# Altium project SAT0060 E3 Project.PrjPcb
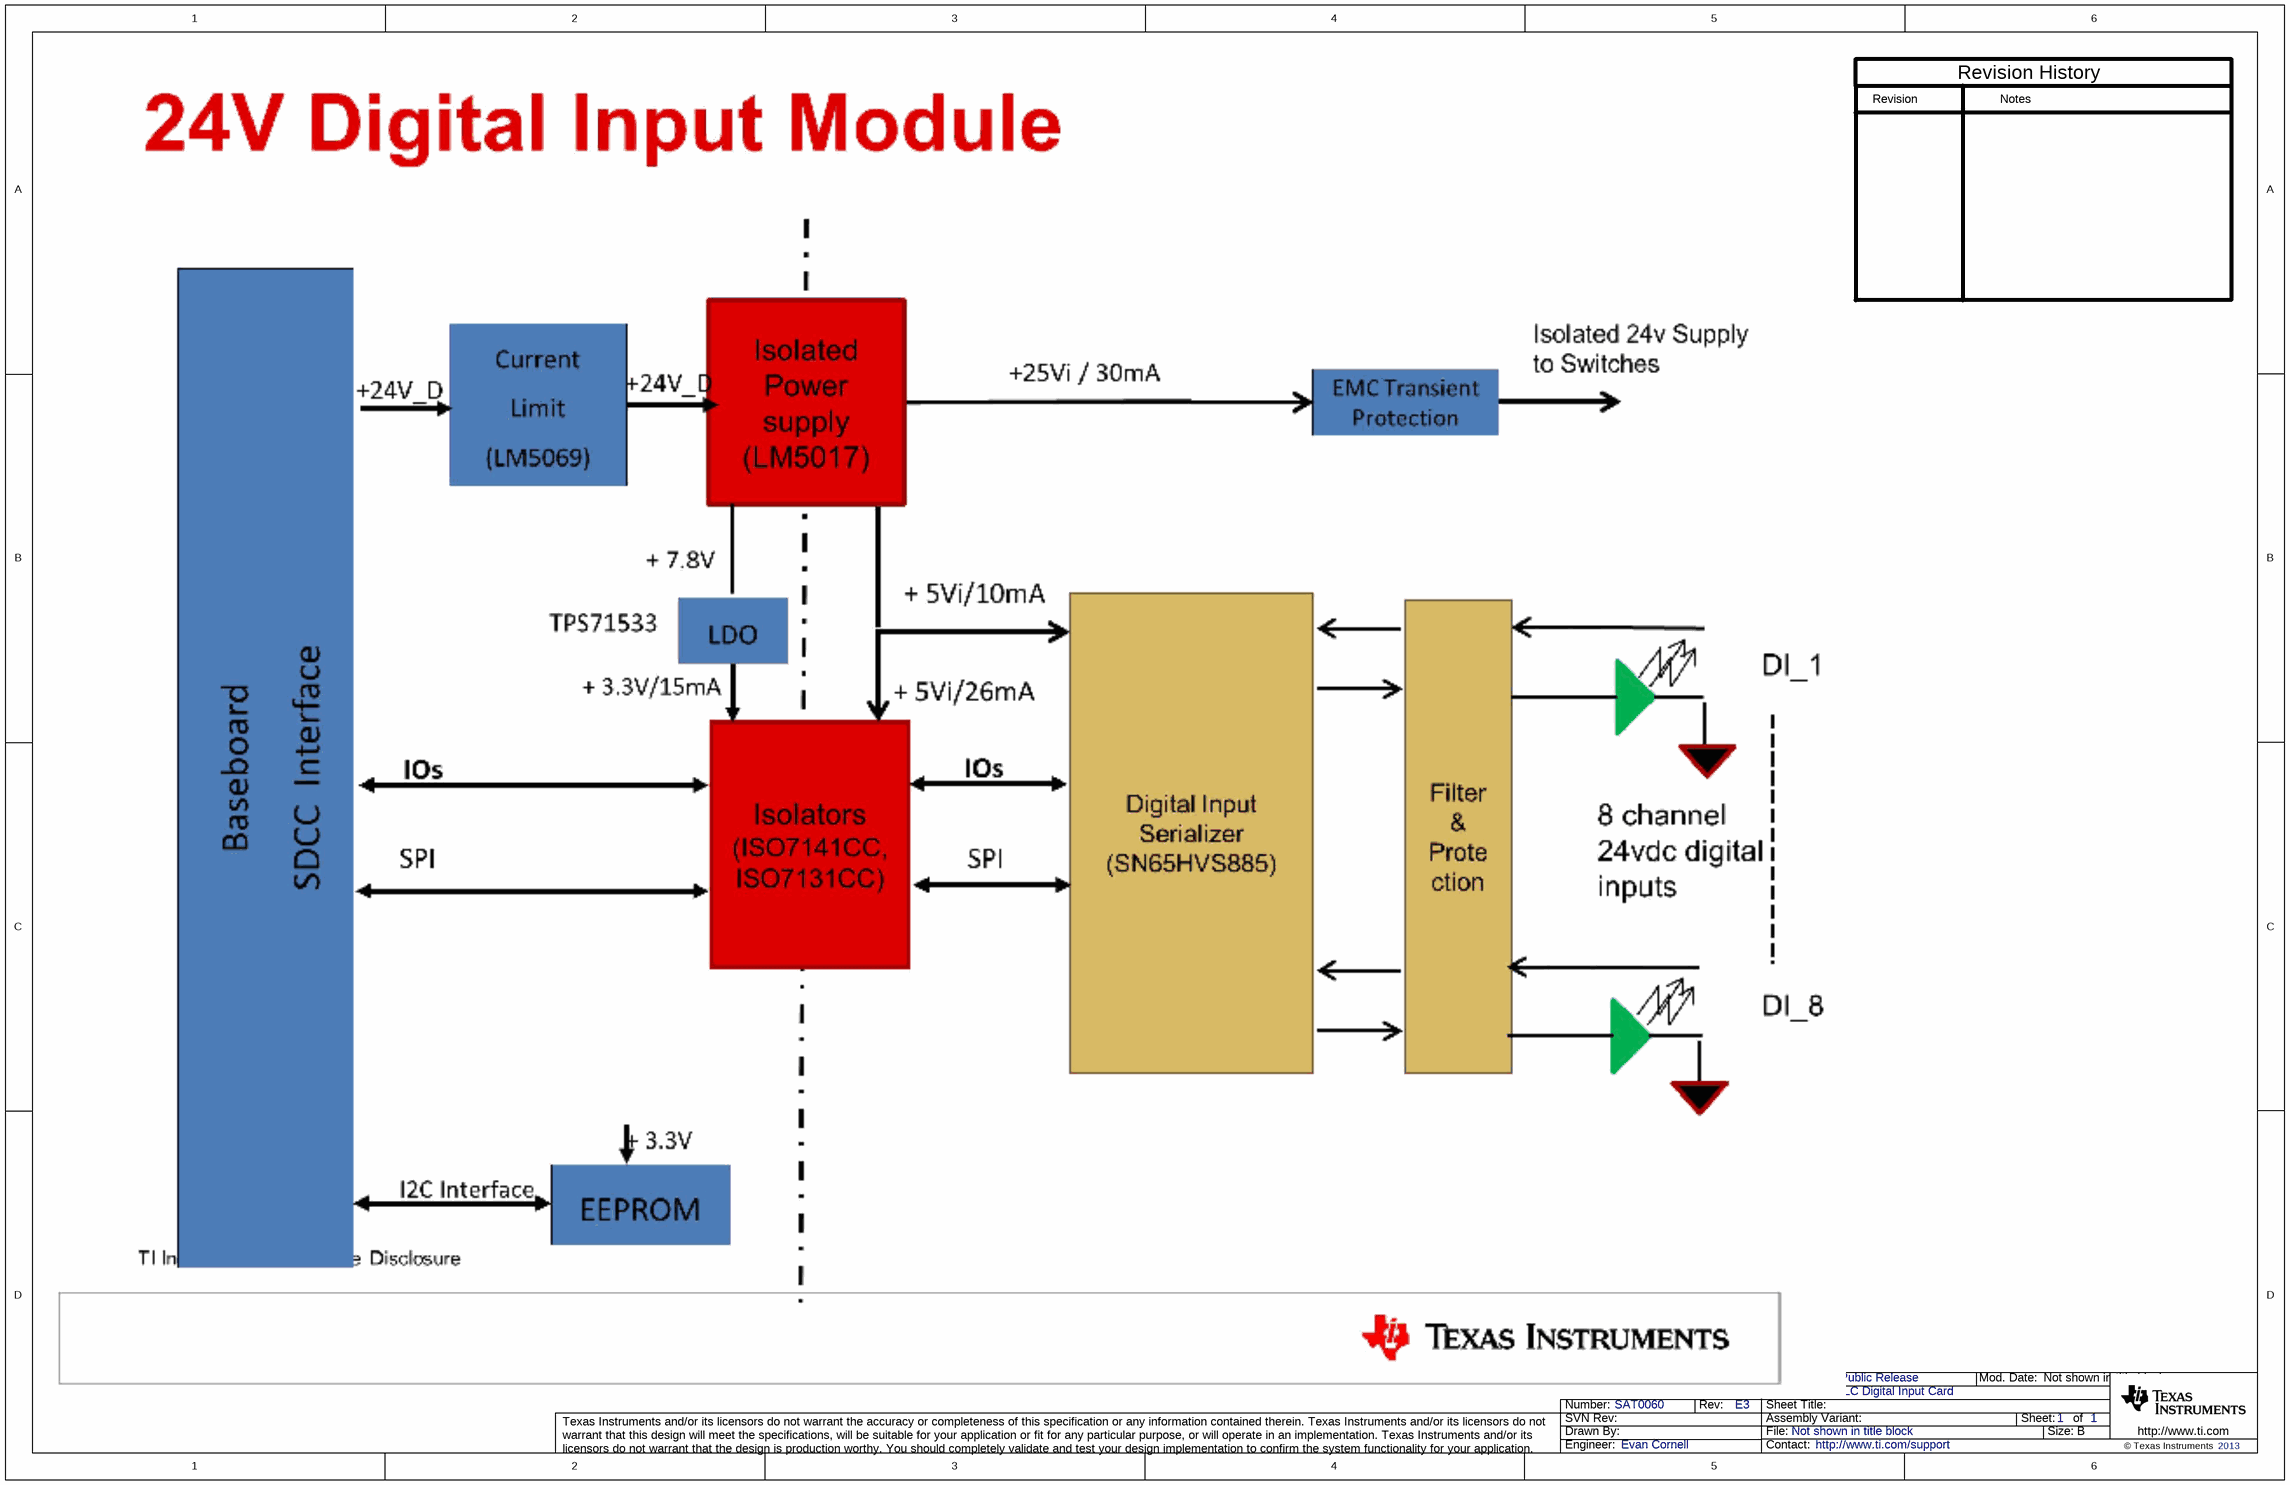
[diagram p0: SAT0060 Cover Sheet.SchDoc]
TechSupport: http://www.ti.com/support; SCH_Rev: E3; PRJ_Title: PLC Digital Input Card; PRJ_Number: SAT0060; PRJ_Engineer: Evan Cornell; PRJ_Customer: Public Release; PCB_Rev: E3; PCB_Layout: TI India; CopyrightYear: 2013
4 sheets, 137 parts. Net scope: global (net labels, ports and power ports of the same name join across sheets).
Board file: SAT0060 E3 PCB.PcbDoc
Sheets:
  SAT0060 Cover Sheet.SchDoc
  SAT0060 Sheet1.SchDoc
  SAT0060 Sheet2.SchDoc
  Hardware_ANSI-B.SchDoc

## Sheet SAT0060 Cover Sheet.SchDoc
size 431 x 279 mm; Date: Not shown in title block; ApprovedBy: Not shown in title block; CheckedBy: Not shown in title block; Author: Not shown in title block; CompanyName: Not shown in title block; Engineer: Not shown in title block; Organization: Not shown in title block; Address1: Not shown in title block; Address2: Not shown in title block; Address3: Not shown in title block; Address4: Not shown in title block; DocumentNumber: 1; Revision: Use project parameter SCH_Rev; SheetNumber: 1; SheetTotal: 1; PageSetup: Record=PageOptions|CenterHorizontal=True|CenterVertical=True|PrintScale=0.96|XCorrection=1.00|YCorrection=1.00|PrintKind=0|BorderSize=5000000|LeftOffset=0|BottomOffset=0|Orientation=2|PaperLength=1000|PaperWidth=1000|Scale=100|PaperSource=15|PrintQuality=600|MediaType=1|DitherType=10|PaperKind=11x17|PrintScaleMode=1

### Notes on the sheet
- Revision
- Notes
- Revision History

## Sheet SAT0060 Sheet1.SchDoc
size 431 x 279 mm; Date: Not shown in title block; ApprovedBy: Not shown in title block; CheckedBy: Not shown in title block; Author: Not shown in title block; CompanyName: Not shown in title block; Engineer: Not shown in title block; Organization: Not shown in title block; Address1: Not shown in title block; Address2: Not shown in title block; Address3: Not shown in title block; Address4: Not shown in title block; DocumentNumber: 1; Revision: Use project parameter SCH_Rev; SheetNumber: 1; SheetTotal: 1; PageSetup: Record=PageOptions|CenterHorizontal=True|CenterVertical=True|PrintScale=0.96|XCorrection=1.00|YCorrection=1.00|PrintKind=0|BorderSize=5000000|LeftOffset=0|BottomOffset=0|Orientation=2|PaperLength=1000|PaperWidth=1000|Scale=100|PaperSource=15|PrintQuality=600|MediaType=1|DitherType=10|PaperKind=11x17|PrintScaleMode=1
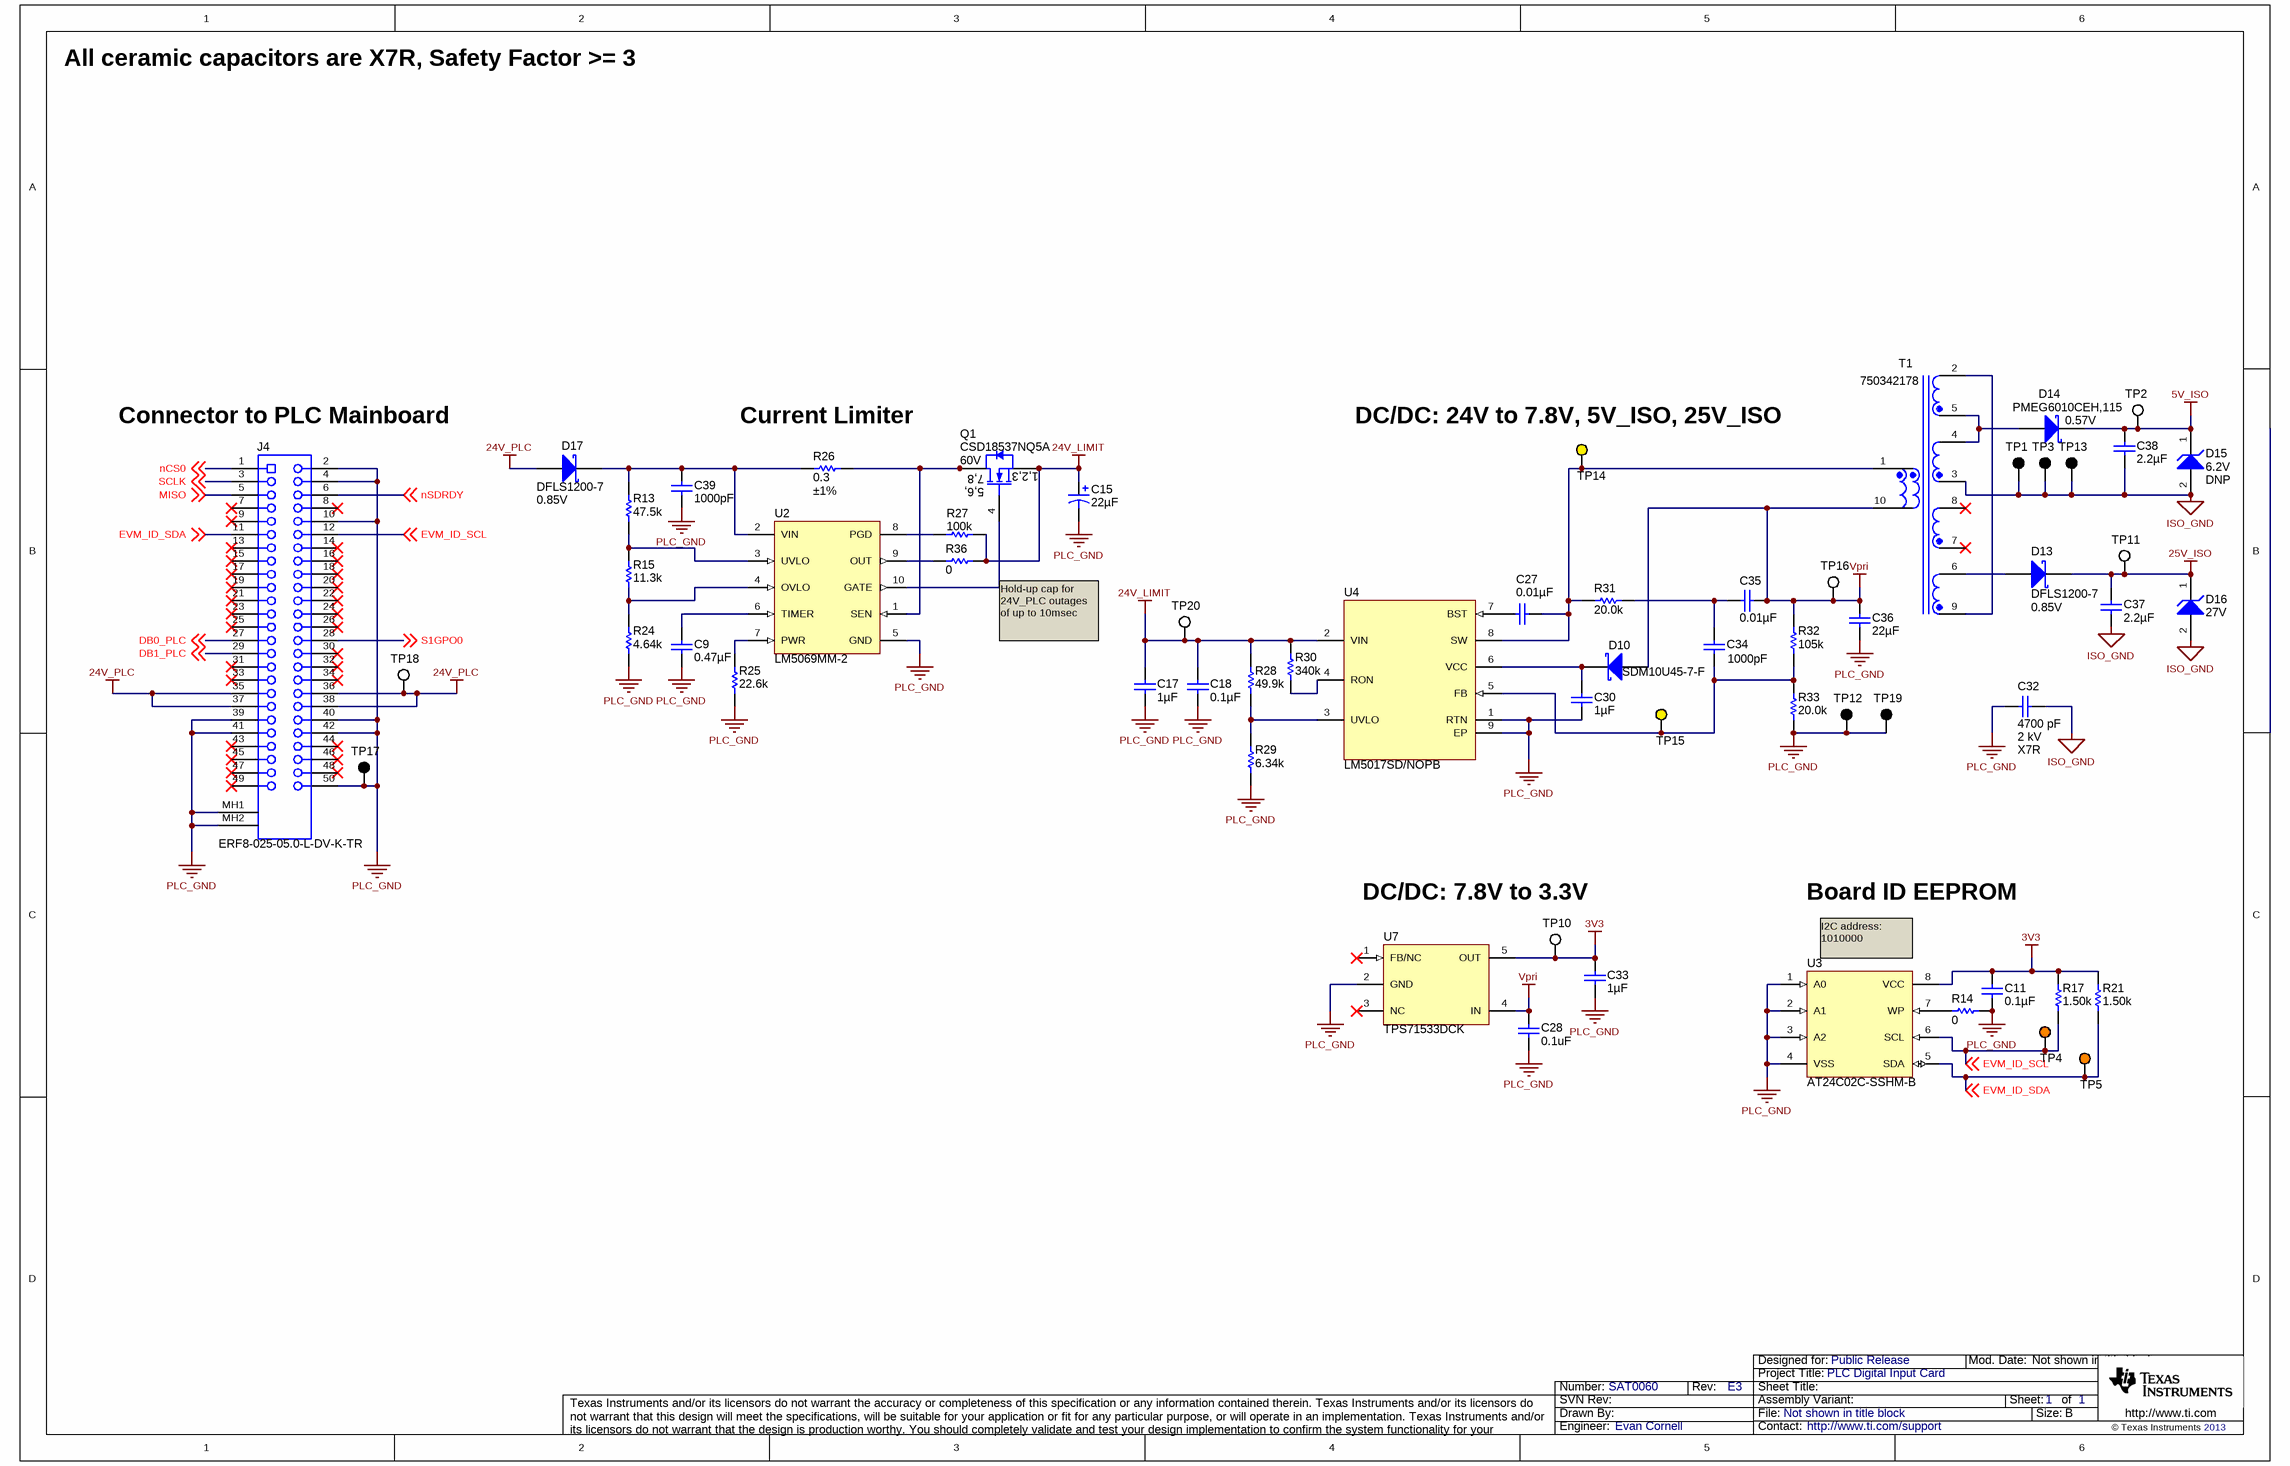
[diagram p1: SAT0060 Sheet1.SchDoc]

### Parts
C9  ValueDisplayed: 0.47µF  [0805_HV]  (hidden comment: 0805YC474JAT2A)
C11  ValueDisplayed: 0.1µF  [0402]  (hidden comment: GRM155R71C104KA88D)
C15  ValueDisplayed: 22µF  [SM_RADIAL_D]  (hidden comment: EEE-FK1H220P)
C17  ValueDisplayed: 1µF  [1206]  (hidden comment: GRM31CR72A105KA01L)
C18  ValueDisplayed: 0.1µF  [0603]  (hidden comment: GRM188R72A104KA35D)
C27  ValueDisplayed: 0.01µF  [0402]  (hidden comment: C1005X7R1C103K)
C28  value 0.1uF  [0603]  (hidden comment: GRM188R71E104KA01D)
C30  ValueDisplayed: 1µF  [0603]  (hidden comment: C1608X7R1C105K)
C32  value 4700 pF  VDC_V: 2 kV  TempCo: X7R  [1210]  (hidden comment: Used in BOM report)
C33  ValueDisplayed: 1µF  [0603]  (hidden comment: GRM188R71C105KA12D)
C34  ValueDisplayed: 1000pF  [0603]  (hidden comment: GRM188R71E102KA01D)
C35  ValueDisplayed: 0.01µF  [0402]  (hidden comment: GRM155R71H103KA88D)
C36  ValueDisplayed: 22µF  [1210]  (hidden comment: GRM32ER71E226KE15L)
C37  ValueDisplayed: 2.2µF  [0805_HV]  (hidden comment: GRM21BR71E225KA73L)
C38  ValueDisplayed: 2.2µF  [0805_HV]  (hidden comment: GRM21BR71E225KA73L)
C39  ValueDisplayed: 1000pF  [0402]  (hidden comment: GRM155R72A102KA01D)
D10  SDM10U45-7-F  [SOD-523]
D13  DFLS1200-7  Value2: 0.85V  [powerDI123]
D14  PMEG6010CEH,115  Value2: 0.57V  [SOD-123F]
D15  value 6.2V  [SOD-123]  (hidden comment: MMSZ5234B-7-F)
D16  value 27V  [SOD-123]  (hidden comment: MMSZ5254B-7-F)
D17  DFLS1200-7  Value2: 0.85V  [powerDI123]
J4  ERF8-025-05.0-L-DV-K-TR  [CONN_ERF8-025-05_0-L-DV-L-TR]
Q1  CSD18537NQ5A  value 60V  [TRANS_NexFET_Q5A]
R13  value 47.5k  [0402]  (hidden comment: CRCW040247K5FKED)
R14  value 0  [0402]  (hidden comment: CRCW04020000Z0ED)
R15  value 11.3k  [0402]  (hidden comment: CRCW040211K3FKED)
R17  value 1.50k  [0402]  (hidden comment: CRCW04021K50FKED)
R21  value 1.50k  [0402]  (hidden comment: CRCW04021K50FKED)
R24  value 4.64k  [0402]  (hidden comment: CRCW04024K64FKED)
R25  value 22.6k  [0402]  (hidden comment: CRCW040222K6FKED)
R26  value 0.3  Tolerance_%: ±1%  [0402]  (hidden comment: Used in BOM report)
R27  value 100k  [0402]  (hidden comment: CRCW0402100KFKED)
R28  value 49.9k  [0402]  (hidden comment: CRCW040249K9FKED)
R29  value 6.34k  [0402]  (hidden comment: CRCW04026K34FKED)
R30  value 340k  [0402]  (hidden comment: CRCW0402340KFKED)
R31  value 20.0k  [0402]  (hidden comment: CRCW040220K0FKED)
R32  value 105k  [0402]  (hidden comment: CRCW0402105KFKED)
R33  value 20.0k  [0402]  (hidden comment: CRCW040220K0FKED)
R36  value 0  [0402]  (hidden comment: CRCW04020000Z0ED)
T1  750342178  [Wurth_750342178]
TP1  5001  [Keystone5001]  (value not drawn)
TP2  5002  [Keystone5002]  (value not drawn)
TP3  5001  [Keystone5001]  (value not drawn)
TP4  5003  [Keystone5003]  (value not drawn)
TP5  5003  [Keystone5003]  (value not drawn)
TP10  5002  [Keystone5002]  (value not drawn)
TP11  5002  [Keystone5002]  (value not drawn)
TP12  5001  [Keystone5001]  (value not drawn)
TP13  5001  [Keystone5001]  (value not drawn)
TP14  5004  [Keystone5004]  (value not drawn)
TP15  5004  [Keystone5004]  (value not drawn)
TP16  5002  [Keystone5002]  (value not drawn)
TP17  5001  [Keystone5001]  (value not drawn)
TP18  5002  [Keystone5002]  (value not drawn)
TP19  5001  [Keystone5001]  (value not drawn)
TP20  5002  [Keystone5002]  (value not drawn)
U2  LM5069MM-2  [MUB10A_N]
U3  AT24C02C-SSHM-B  [SOIC-8]
U4  LM5017SD/NOPB  [NGU0008B]
U7  TPS71533DCK  [DCK0005A_N]

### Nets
3V3: C11.1 C33.1 R17.2 R21.2 TP10.1 U3.8(VCC) U7.5(OUT)
5V_ISO: C38.1 D14.1(K) D15.1(K) TP2.1
24V_LIMIT: C15.1(+) C17.1 C18.1 Q1.1(S) Q1.2(S) Q1.3(S) R27.1 R28.2 R30.2 R36.1 TP20.1 U4.2(VIN)
24V_PLC: D17.2(A) J4.35 J4.36 J4.37 J4.38 TP18.1
25V_ISO: C37.1 D13.1(K) D16.1(K) TP11.1
ISO_GND: C32.1 C37.2 C38.2 D15.2(A) D16.2(A) T1.3 TP1.1 TP3.1 TP13.1
PLC_GND: C9.2 C11.2 C15.2(-) C17.2 C18.2 C28.1 C30.2 C32.2 C33.2 C36.2 C39.2 J4.2 J4.4 J4.10 J4.39 J4.40 J4.41 J4.42 J4.50 J4.MH1 J4.MH2 R14.2 R24.1 R25.1 R29.1 R33.1 TP12.1 TP17.1 TP19.1 U2.5(GND) U3.1(A0) U3.2(A1) U3.3(A2) U3.4(VSS) U4.1(RTN) U4.9(EP) U7.2(GND)
Vpri: C28.2 C35.1 C36.1 D10.2(A) R32.2 T1.10 TP16.1 U7.4(IN)
DB0_PLC: J4.27 ; off-sheet DB0_PLC
DB1_PLC: J4.29 ; off-sheet DB1_PLC
EVM_ID_SCL: J4.12 R17.1 TP4.1 U3.6(SCL) ; off-sheet EVM_ID_SCL
EVM_ID_SDA: J4.11 R21.1 TP5.1 U3.5(SDA) ; off-sheet EVM_ID_SDA
MISO: J4.5 ; off-sheet MISO
nCS0: J4.1 ; off-sheet nCS0
nSDRDY: J4.6 ; off-sheet nSDRDY
S1GPO0: J4.28 ; off-sheet S1GPO0
SCLK: J4.3 ; off-sheet SCLK
NetC9_1: C9.1 U2.6(TIMER)
NetC27_1: C27.1 U4.7(BST)
NetC27_2: C27.2 R31.1 T1.1 TP14.1 U4.8(SW)
NetC30_1: C30.1 D10.1(K) U4.6(VCC)
NetC34_1: C34.1 C35.2 R31.2
NetC34_2: C34.2 R32.1 R33.2 TP15.1 U4.5(FB)
NetC39_1: C39.1 D17.1(K) R13.2 R26.1 U2.2(VIN)
NetD13_2: D13.2(A) T1.6
NetD14_2: D14.2(A) T1.4 T1.5
NetQ1_4: Q1.4(G) U2.10(GATE)
NetQ1_5: Q1.5(D) Q1.6(D) Q1.7(D) Q1.8(D) Q1.9(D) R26.2 U2.1(SEN)
NetR13_1: R13.1 R15.2 U2.3(UVLO)
NetR14_1: R14.1 U3.7(WP)
NetR15_1: R15.1 R24.2 U2.4(OVLO)
NetR25_2: R25.2 U2.7(PWR)
NetR27_2: R27.2 U2.8(PGD)
NetR28_1: R28.1 R29.2 U4.3(UVLO)
NetR30_1: R30.1 U4.4(RON)
NetR36_2: R36.2 U2.9(OUT)
NetT1_2: T1.2 T1.9

Not connected (* = marked no-connect by the designer): J4 7* 8* 9* 13* 14* 15* 16* 17* 18* 19* 20* 21* 22* 23* 24* 25* 26* 30* 31* 32* 33* 34* 43* 44* 45* 46* 47* 48* 49*; T1 7* 8*; U7 1(FB/NC)* 3(NC)*

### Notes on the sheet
- All ceramic capacitors are X7R, Safety Factor >= 3
- (near J4) Connector to PLC Mainboard
- (near R26) Current Limiter
- (near TP14) DC/DC: 24V to 7.8V, 5V_ISO, 25V_ISO
- Hold-up cap for 24V_PLC outages of up to 10msec
- DC/DC: 7.8V to 3.3V
- Board ID EEPROM
- (near U3) I2C address: 1010000

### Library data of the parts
C9 = 0805YC474JAT2A: CAP, CERM, 0.47uF, 16V, +/-5%, X7R, 0805; Manufacturer: AVX; Polarized: N; CompType: Capacitor; U/M: EA; Cap_F: 0.00000047; Tolerance_%: 5; ESR_Ohm: 0.011; Value1: 0.011 ohm; VDC_V: 16; TaMin_C: -55; TaMax_C: 125; Cap_Case: 0805
C11 = GRM155R71C104KA88D: CAP, CERM, 0.1uF, 16V, +/-10%, X7R, 0402; Manufacturer: MuRata; Polarized: N; CompType: Capacitor; U/M: EA; Cap_F: 0.0000001; Tolerance_%: 10; Value1: Unknown; VDC_V: 16; TaMin_C: -55; TaMax_C: 125
C15 = EEE-FK1H220P: CAP, AL, 22uF, 50V, +/-20%, 0.88 ohm, SMD; Manufacturer: Panasonic; Polarized: Y; CompType: Capacitor; U/M: EA; Cap_F: 0.000022; Tolerance_%: 20; VDC_V: 50; ESR_Ohm: 0.88; IRMS_A: 0.165; TaMin_C: -55; TaMax_C: 105; Cap_Case: D
C17 = GRM31CR72A105KA01L: CAP, CERM, 1uF, 100V, +/-10%, X7R, 1206; Manufacturer: MuRata; Polarized: N; CompType: Capacitor; U/M: EA; Cap_F: 0.000001; Tolerance_%: 10; Value1: Unknown; VDC_V: 100; TaMin_C: -55; TaMax_C: 125; Cap_Case: 2220
C18 = GRM188R72A104KA35D: CAP, CERM, 0.1uF, 100V, +/-10%, X7R, 0603; Manufacturer: MuRata; Polarized: N; CompType: Capacitor; U/M: EA; Cap_F: 0.0000001; Tolerance_%: 10; Value1: Unknown; VDC_V: 100; TaMin_C: -55; TaMax_C: 125
C27 = C1005X7R1C103K: CAP, CERM, 0.01uF, 16V, +/-10%, X7R, 0402; Manufacturer: TDK; Polarized: N; CompType: Capacitor; U/M: EA; Cap_F: 0.00000001; Tolerance_%: 10; ESR_Ohm: 0.0623; Value1: 0.0623 ohm; VDC_V: 16; TaMin_C: -55; TaMax_C: 125
C28 = GRM188R71E104KA01D: CAP, CERM, 0.1uF, 25V, +/-10%, X7R, 0603; Manufacturer: MuRata; Polarized: N; CompType: Capacitor; U/M: EA; Cap_F: 0.0000001; Tolerance_%: 10; VDC_V: 25; TaMin_C: -55; TaMax_C: 125; ValueDisplayed: 0.1µF
C30 = C1608X7R1C105K: CAP, CERM, 1uF, 16V, +/-10%, X7R, 0603; Manufacturer: TDK; Polarized: N; CompType: Capacitor; U/M: EA; Cap_F: 0.000001; Tolerance_%: 10; ESR_Ohm: 0.0057; Value1: 0.0057 ohm; VDC_V: 16; TaMin_C: -55; TaMax_C: 125
C32 = Capacitor: CAP, CERM, xxxF, xxV, [TempCo], xx%, [PackageReference]; Polarized: N; U/M: EA; Description: Multilayer Ceramic Capacitors MLCC - SMD/SMT 2000volts 4700pF 10% X7R; Tolerance_%: 10 %; Capacitance - nF: 4.7 nF; Capacitance - uF: 0.0047 uF; Class: 2
C33 = GRM188R71C105KA12D: CAP, CERM, 1uF, 16V, +/-10%, X7R, 0603; Manufacturer: MuRata; Polarized: N; CompType: Capacitor; U/M: EA; Cap_F: 0.000001; Tolerance_%: 10; ESR_Ohm: 0.011; Value1: 0.011 ohm; VDC_V: 16; TaMin_C: -55; TaMax_C: 125
C34 = GRM188R71E102KA01D: CAP, CERM, 1000pF, 25V, +/-10%, X7R, 0603; Manufacturer: MuRata; Polarized: N; CompType: Capacitor; U/M: EA; Cap_F: 0.000000001; Tolerance_%: 10; Value1: Unknown; VDC_V: 25; TaMin_C: -55; TaMax_C: 125
C35 = GRM155R71H103KA88D: CAP, CERM, 0.01uF, 50V, +/-10%, X7R, 0402; Manufacturer: MuRata; Polarized: N; CompType: Capacitor; U/M: EA; Cap_F: 0.00000001; Tolerance_%: 10; Value1: Unknown; VDC_V: 50; TaMin_C: -55; TaMax_C: 125
C36 = GRM32ER71E226KE15L: CAP, CERM, 22uF, 25V, +/-10%, X7R, 1210; Manufacturer: MuRata; Polarized: N; CompType: Capacitor; U/M: EA; Cap_F: 0.000022; Tolerance_%: 10; Value1: Unknown; VDC_V: 25; TaMin_C: -55; TaMax_C: 125
C37 C38 = GRM21BR71E225KA73L: CAP, CERM, 2.2uF, 25V, +/-10%, X7R, 0805; Manufacturer: MuRata; Polarized: N; CompType: Capacitor; U/M: EA; Cap_F: 0.0000022; Tolerance_%: 10; ESR_Ohm: 0.005; Value1: 0.005 ohm; VDC_V: 25; TaMin_C: -55; TaMax_C: 125; Cap_Case: 0805
C39 = GRM155R72A102KA01D: CAP, CERM, 1000pF, 100V, +/-10%, X7R, 0402; Manufacturer: MuRata; Polarized: N; CompType: Capacitor; U/M: EA; Cap_F: 0.000000001; Tolerance_%: 10; Value1: Unknown; VDC_V: 100; TaMin_C: -55; TaMax_C: 125
D10 = SDM10U45-7-F: Diode, Schottky, 45V, 0.1A, SOD-523; Manufacturer: Diodes Inc.; U/M: EA; Vf_V: 0.58; Value2: 0.58V; Io_A: 0.1; Vr_V: 45; TJmax_C: 125
D13 D17 = DFLS1200-7: Diode, Schottky, 200V, 1A, PowerDI123; Manufacturer: Diodes Inc.; U/M: EA; Vf_V: 0.85; Io_A: 1; Vr_V: 200; TJmax_C: 175; RJC_CperW: 7
D14 = PMEG6010CEH,115: Diode, Schottky, 60V, 1A, SOD-123F; Manufacturer: NXP Semiconductor; U/M: EA; Vf_V: 0.57; Io_A: 1; Vr_V: 60; TJmax_C: 150
D15 = MMSZ5234B-7-F: Diode, Zener, 6.2V, 500mW, SOD-123; Manufacturer: Diodes Inc.; U/M: EA; Power_W: 0.5; Vz_V: 6.2; Value1: 0.5W; RJA_CperW: 350
D16 = MMSZ5254B-7-F: Diode, Zener, 27V, 500mW, SOD-123; Manufacturer: Diodes Inc.; U/M: EA; Power_W: 0.5; Vz_V: 27; Value1: 0.5W; RJA_CperW: 350
J4 = ERF8-025-05.0-L-DV-K-TR: Receptacle, 0.8mm, 25x2, SMT; Manufacturer: Samtec; SymbolCreator: a0412235; CompType: Connector; U/M: EA
Q1 = CSD18537NQ5A: MOSFET, N-CH, 60V, 50A, SON 5x6mm; Manufacturer: Texas Instruments; Alternate Manufacturer: None; U/M: EA; ChType: N; VdsMax_V: 60; Value1: 0.036 ohm; Rdson45_Ohm: 0.036; Value2: 14 nC; QgTyp_nC: 14; Vgs_V: 20; IdsMax_A: 50
R13 = CRCW040247K5FKED: RES, 47.5k ohm, 1%, 0.063W, 0402; Manufacturer: Vishay-Dale; CompType: Resistor; Res_ohm: 47500; Value_Code: 47k5; Tolerance_%: 1; Power_W: 0.063; VDC_V: 50; TempCo: 100 ppm/C; EIA_Code: E96; U/M: EA
R14 R36 = CRCW04020000Z0ED: RES, 0 ohm, 5%, 0.063W, 0402; Manufacturer: Vishay-Dale; CompType: Resistor; Value_Code: 0000; Tolerance_%: 5; Power_W: 0.063; VDC_V: 50; TempCo: 200 ppm/C; EIA_Code: E24; U/M: EA
R15 = CRCW040211K3FKED: RES, 11.3k ohm, 1%, 0.063W, 0402; Manufacturer: Vishay-Dale; CompType: Resistor; Res_ohm: 11300; Value_Code: 11k3; Tolerance_%: 1; Power_W: 0.063; VDC_V: 50; TempCo: 100 ppm/C; EIA_Code: E96; U/M: EA
R17 R21 = CRCW04021K50FKED: RES, 1.50k ohm, 1%, 0.063W, 0402; Manufacturer: Vishay-Dale; CompType: Resistor; Res_ohm: 1500; Value_Code: 1k50; Tolerance_%: 1; Power_W: 0.063; VDC_V: 50; TempCo: 100 ppm/C; EIA_Code: E96; U/M: EA
R24 = CRCW04024K64FKED: RES, 4.64k ohm, 1%, 0.063W, 0402; Manufacturer: Vishay-Dale; CompType: Resistor; Res_ohm: 4640; Value_Code: 4k64; Tolerance_%: 1; Power_W: 0.063; VDC_V: 50; TempCo: 100 ppm/C; EIA_Code: E96; U/M: EA
R25 = CRCW040222K6FKED: RES, 22.6k ohm, 1%, 0.063W, 0402; Manufacturer: Vishay-Dale; CompType: Resistor; Res_ohm: 22600; Value_Code: 22k6; Tolerance_%: 1; Power_W: 0.063; VDC_V: 50; TempCo: 100 ppm/C; EIA_Code: E96; U/M: EA
R26 = Resistor: RES, xxx ohm, x%, xW, [PackageReference]; U/M: EA; Description: RES 0.3 OHM 1/8W 1% 0402; Power_W: 0.125W, 1/8W; TempCo: ±300ppm/°C
R27 = CRCW0402100KFKED: RES, 100k ohm, 1%, 0.063W, 0402; Manufacturer: Vishay-Dale; CompType: Resistor; Res_ohm: 100000; Tolerance_%: 1; Power_W: 0.063; VDC_V: 50; TempCo: 100 ppm/C; EIA_Code: E96; U/M: EA
R28 = CRCW040249K9FKED: RES, 49.9k ohm, 1%, 0.063W, 0402; Manufacturer: Vishay-Dale; CompType: Resistor; Res_ohm: 49900; Value_Code: 49k9; Tolerance_%: 1; Power_W: 0.063; VDC_V: 50; TempCo: 100 ppm/C; EIA_Code: E96; U/M: EA
R29 = CRCW04026K34FKED: RES, 6.34k ohm, 1%, 0.063W, 0402; Manufacturer: Vishay-Dale; CompType: Resistor; Res_ohm: 6340; Value_Code: 6k34; Tolerance_%: 1; Power_W: 0.063; VDC_V: 50; TempCo: 100 ppm/C; EIA_Code: E96; U/M: EA
R30 = CRCW0402340KFKED: RES, 340k ohm, 1%, 0.063W, 0402; Manufacturer: Vishay-Dale; CompType: Resistor; Res_ohm: 340000; Tolerance_%: 1; Power_W: 0.063; VDC_V: 50; TempCo: 100 ppm/C; EIA_Code: E96; U/M: EA
R31 R33 = CRCW040220K0FKED: RES, 20.0k ohm, 1%, 0.063W, 0402; Manufacturer: Vishay-Dale; CompType: Resistor; Res_ohm: 20000; Value_Code: 20k0; Tolerance_%: 1; Power_W: 0.063; VDC_V: 50; TempCo: 100 ppm/C; EIA_Code: E96; U/M: EA
R32 = CRCW0402105KFKED: RES, 105k ohm, 1%, 0.063W, 0402; Manufacturer: Vishay-Dale; CompType: Resistor; Res_ohm: 105000; Tolerance_%: 1; Power_W: 0.063; VDC_V: 50; TempCo: 100 ppm/C; EIA_Code: E96; U/M: EA
T1 = 750342178: Transformer, 50 uH, SMT; Manufacturer: Wurth Elektronik eiSos; SymbolCreator: a0799628; DCR_Ohm: 0.15; Value: 50 uH; LeakageL: 2.0 uH; U/M: EA
TP1 TP3 TP12 TP13 TP17 TP19 = 5001: Test Point, Miniature, Black, TH; Manufacturer: Keystone; CompType: Test Point Loop; U/M: EA
TP2 TP10 TP11 TP16 TP18 TP20 = 5002: Test Point, Miniature, White, TH; Manufacturer: Keystone; CompType: Test Point Loop; U/M: EA
TP4 TP5 = 5003: Test Point, Miniature, Orange, TH; Manufacturer: Keystone; CompType: Test Point Loop; U/M: EA
TP14 TP15 = 5004: Test Point, Miniature, Yellow, TH; Manufacturer: Keystone; CompType: Test Point Loop; U/M: EA
U2 = LM5069MM-2: Positive High Voltage Hot Swap / Inrush Current Controller with Power Limiting, 10-pin MSOP; Manufacturer: National Semiconductor; PackageTopMarking: ZXTT*SNBB; PowerWise: N; CompType: MiscPower
U3 = AT24C02C-SSHM-B: IC, EEPROM, 2KBIT, 1MHZ, SOIC-8; Manufacturer: Atmel; SymbolCreator: a0411947
U4 = LM5017SD/NOPB: 100V, 600mA Constant On-Time Synchronous Buck Regulator, NGU0008B; Alternate Manufacturer: None; Manufacturer: Texas Instruments; SymbolCreator: a0412235; CompType: IC; U/M: EA
U7 = TPS71533DCK: 50 mA, 24 V, 3.2-mA Supply Current Low-Dropout Linear Regulator, DCK0005A; Alternate Manufacturer: None; Manufacturer: Texas Instruments; SymbolCreator: a0799628; CompType: IC; U/M: EA

## Sheet SAT0060 Sheet2.SchDoc
size 431 x 279 mm; Date: Not shown in title block; ApprovedBy: Not shown in title block; CheckedBy: Not shown in title block; Author: Not shown in title block; CompanyName: Not shown in title block; Engineer: Not shown in title block; Organization: Not shown in title block; Address1: Not shown in title block; Address2: Not shown in title block; Address3: Not shown in title block; Address4: Not shown in title block; DocumentNumber: 1; Revision: Use project parameter SCH_Rev; SheetNumber: 1; SheetTotal: 1; PageSetup: Record=PageOptions|CenterHorizontal=True|CenterVertical=True|PrintScale=0.96|XCorrection=1.00|YCorrection=1.00|PrintKind=0|BorderSize=5000000|LeftOffset=0|BottomOffset=0|Orientation=2|PaperLength=1000|PaperWidth=1000|Scale=100|PaperSource=15|PrintQuality=600|MediaType=1|DitherType=10|PaperKind=11x17|PrintScaleMode=1
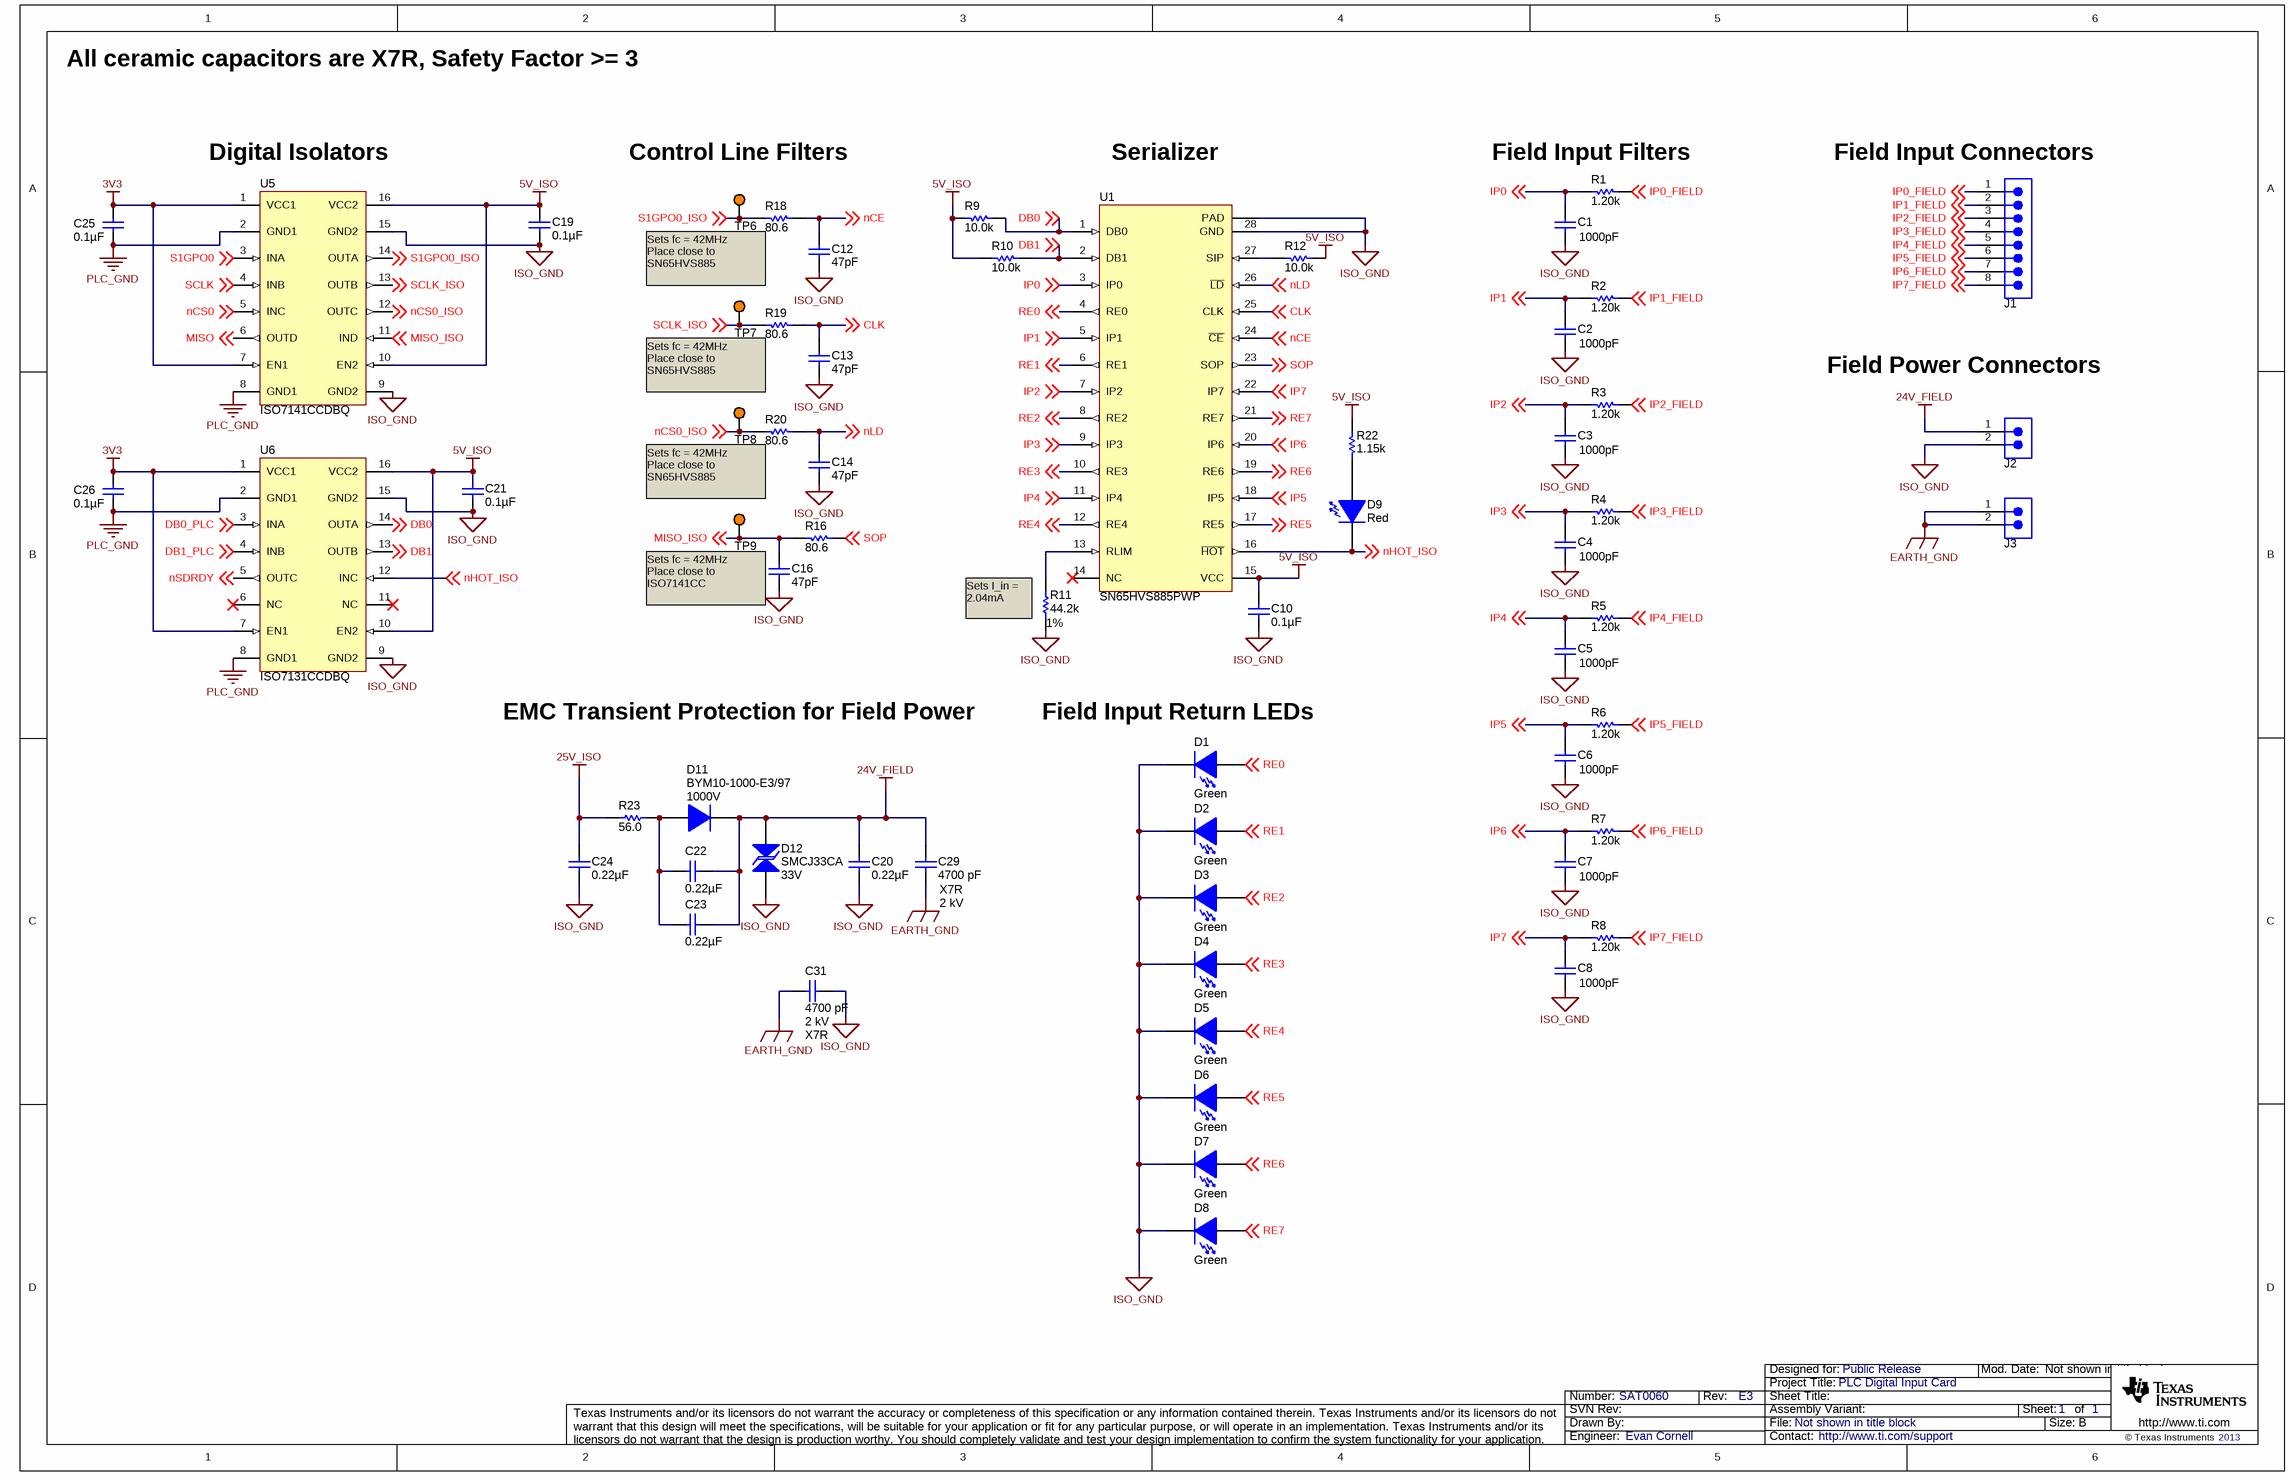
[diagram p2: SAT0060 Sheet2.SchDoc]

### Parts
C1  value 1000pF  [1206]  (hidden comment: 202R18W102KV4E)
C2  value 1000pF  [1206]  (hidden comment: 202R18W102KV4E)
C3  value 1000pF  [1206]  (hidden comment: 202R18W102KV4E)
C4  value 1000pF  [1206]  (hidden comment: 202R18W102KV4E)
C5  value 1000pF  [1206]  (hidden comment: 202R18W102KV4E)
C6  value 1000pF  [1206]  (hidden comment: 202R18W102KV4E)
C7  value 1000pF  [1206]  (hidden comment: 202R18W102KV4E)
C8  value 1000pF  [1206]  (hidden comment: 202R18W102KV4E)
C10  ValueDisplayed: 0.1µF  [0402]  (hidden comment: GRM155R71C104KA88D)
C12  ValueDisplayed: 47pF  [0402]  (hidden comment: GRM1555C1H470JZ01)
C13  ValueDisplayed: 47pF  [0402]  (hidden comment: GRM1555C1H470JZ01)
C14  ValueDisplayed: 47pF  [0402]  (hidden comment: GRM1555C1H470JZ01)
C16  ValueDisplayed: 47pF  [0402]  (hidden comment: GRM1555C1H470JZ01)
C19  ValueDisplayed: 0.1µF  [0402]  (hidden comment: GRM155R71C104KA88D)
C20  ValueDisplayed: 0.22µF  [0805_HV]  (hidden comment: GRM21AR72A224KAC5L)
C21  ValueDisplayed: 0.1µF  [0402]  (hidden comment: GRM155R71C104KA88D)
C22  ValueDisplayed: 0.22µF  [0805_HV]  (hidden comment: GRM21AR72A224KAC5L)
C23  ValueDisplayed: 0.22µF  [0805_HV]  (hidden comment: GRM21AR72A224KAC5L)
C24  ValueDisplayed: 0.22µF  [0805_HV]  (hidden comment: GRM21AR72A224KAC5L)
C25  ValueDisplayed: 0.1µF  [0402]  (hidden comment: GRM155R71C104KA88D)
C26  ValueDisplayed: 0.1µF  [0402]  (hidden comment: GRM155R71C104KA88D)
C29  value 4700 pF  VDC_V: 2 kV  TempCo: X7R  [1210]  (hidden comment: Used in BOM report)
C31  value 4700 pF  VDC_V: 2 kV  TempCo: X7R  [1210]  (hidden comment: Used in BOM report)
D1  Color: Green  [SML-P12PTT86]  (hidden comment: SML-P12PTT86)
D2  Color: Green  [SML-P12PTT86]  (hidden comment: SML-P12PTT86)
D3  Color: Green  [SML-P12PTT86]  (hidden comment: SML-P12PTT86)
D4  Color: Green  [SML-P12PTT86]  (hidden comment: SML-P12PTT86)
D5  Color: Green  [SML-P12PTT86]  (hidden comment: SML-P12PTT86)
D6  Color: Green  [SML-P12PTT86]  (hidden comment: SML-P12PTT86)
D7  Color: Green  [SML-P12PTT86]  (hidden comment: SML-P12PTT86)
D8  Color: Green  [SML-P12PTT86]  (hidden comment: SML-P12PTT86)
D9  Color: Red  [SML-P12VTT86]  (hidden comment: SML-P12VTT86)
D11  BYM10-1000-E3/97  value 1000V  [DO-213AB]
D12  SMCJ33CA  value 33V  [SMC]
J1  1725711  [CONN_1725711]  (value not drawn)
J2  1725656  [CONN_1725656]  (value not drawn)
J3  1725656  [CONN_1725656]  (value not drawn)
R1  value 1.20k  [MMA0204]  (hidden comment: MMA02040C1201FB300)
R2  value 1.20k  [MMA0204]  (hidden comment: MMA02040C1201FB300)
R3  value 1.20k  [MMA0204]  (hidden comment: MMA02040C1201FB300)
R4  value 1.20k  [MMA0204]  (hidden comment: MMA02040C1201FB300)
R5  value 1.20k  [MMA0204]  (hidden comment: MMA02040C1201FB300)
R6  value 1.20k  [MMA0204]  (hidden comment: MMA02040C1201FB300)
R7  value 1.20k  [MMA0204]  (hidden comment: MMA02040C1201FB300)
R8  value 1.20k  [MMA0204]  (hidden comment: MMA02040C1201FB300)
R9  value 10.0k  [0402]  (hidden comment: CRCW040210K0FKED)
R10  value 10.0k  [0402]  (hidden comment: CRCW040210K0FKED)
R11  value 44.2k  Value1: 1%  [0402]  (hidden comment: CRCW040244K2FKED)
R12  value 10.0k  [0402]  (hidden comment: CRCW040210K0FKED)
R16  value 80.6  [0402]  (hidden comment: CRCW040280R6FKED)
R18  value 80.6  [0402]  (hidden comment: CRCW040280R6FKED)
R19  value 80.6  [0402]  (hidden comment: CRCW040280R6FKED)
R20  value 80.6  [0402]  (hidden comment: CRCW040280R6FKED)
R22  value 1.15k  [0402]  (hidden comment: CRCW04021K15FKED)
R23  value 56.0  [MMB0207]  (hidden comment: MMB02070C5609FB200)
TP6  5003  [Keystone5003]  (value not drawn)
TP7  5003  [Keystone5003]  (value not drawn)
TP8  5003  [Keystone5003]  (value not drawn)
TP9  5003  [Keystone5003]  (value not drawn)
U1  SN65HVS885PWP  [PWP0028E_N]
U5  ISO7141CCDBQ  [DBQ0016A_N]
U6  ISO7131CCDBQ  [DBQ0016A_N]

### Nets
3V3: C25.1 C26.1 U5.1(VCC1) U5.7(EN1) U6.1(VCC1) U6.7(EN1)
5V_ISO: C10.1 C19.1 C21.1 R9.2 R10.2 R12.1 R22.2 U1.15(VCC) U5.10(EN2) U5.16(VCC2) U6.10(EN2) U6.16(VCC2)
24V_FIELD: C20.1 C22.2 C23.2 C29.1 D11.1(K) D12.2 J2.1
25V_ISO: C24.1 R23.1
EARTH_GND: C29.2 C31.1 J3.1 J3.2
ISO_GND: C1.2 C2.2 C3.2 C4.2 C5.2 C6.2 C7.2 C8.2 C10.2 C12.2 C13.2 C14.2 C16.2 C19.2 C20.2 C21.2 C24.2 C31.2 D1.2(K) D2.2(K) D3.2(K) D4.2(K) D5.2(K) D6.2(K) D7.2(K) D8.2(K) D12.1 J2.2 R11.1 U1.28(GND) U1.29(PAD) U5.9(GND2) U5.15(GND2) U6.9(GND2) U6.15(GND2)
PLC_GND: C25.2 C26.2 U5.2(GND1) U5.8(GND1) U6.2(GND1) U6.8(GND1)
CLK: C13.1 R19.1 U1.25(CLK) ; off-sheet CLK
DB0: R9.1 U1.1(DB0) U6.14(OUTA) ; off-sheet DB0
DB0_PLC: U6.3(INA) ; off-sheet DB0_PLC
DB1: R10.1 U1.2(DB1) U6.13(OUTB) ; off-sheet DB1
DB1_PLC: U6.4(INB) ; off-sheet DB1_PLC
IP0: C1.1 R1.2 U1.3(IP0) ; off-sheet IP0
IP0_FIELD: J1.1 R1.1 ; off-sheet IP0_FIELD
IP1: C2.1 R2.2 U1.5(IP1) ; off-sheet IP1
IP1_FIELD: J1.2 R2.1 ; off-sheet IP1_FIELD
IP2: C3.1 R3.2 U1.7(IP2) ; off-sheet IP2
IP2_FIELD: J1.3 R3.1 ; off-sheet IP2_FIELD
IP3: C4.1 R4.2 U1.9(IP3) ; off-sheet IP3
IP3_FIELD: J1.4 R4.1 ; off-sheet IP3_FIELD
IP4: C5.1 R5.2 U1.11(IP4) ; off-sheet IP4
IP4_FIELD: J1.5 R5.1 ; off-sheet IP4_FIELD
IP5: C6.1 R6.2 U1.18(IP5) ; off-sheet IP5
IP5_FIELD: J1.6 R6.1 ; off-sheet IP5_FIELD
IP6: C7.1 R7.2 U1.20(IP6) ; off-sheet IP6
IP6_FIELD: J1.7 R7.1 ; off-sheet IP6_FIELD
IP7: C8.1 R8.2 U1.22(IP7) ; off-sheet IP7
IP7_FIELD: J1.8 R8.1 ; off-sheet IP7_FIELD
MISO: U5.6(OUTD) ; off-sheet MISO
MISO_ISO: C16.1 R16.2 TP9.1 U5.11(IND) ; off-sheet MISO_ISO
nCE: C12.1 R18.1 U1.24(~{CE}) ; off-sheet nCE
nCS0: U5.5(INC) ; off-sheet nCS0
nCS0_ISO: R20.2 TP8.1 U5.12(OUTC) ; off-sheet nCS0_ISO
nHOT_ISO: D9.2(K) U1.16(~{HOT}) U6.12(INC) ; off-sheet nHOT_ISO
nLD: C14.1 R20.1 U1.26(~{LD}) ; off-sheet nLD
nSDRDY: U6.5(OUTC) ; off-sheet nSDRDY
RE0: D1.1(A) U1.4(RE0) ; off-sheet RE0
RE1: D2.1(A) U1.6(RE1) ; off-sheet RE1
RE2: D3.1(A) U1.8(RE2) ; off-sheet RE2
RE3: D4.1(A) U1.10(RE3) ; off-sheet RE3
RE4: D5.1(A) U1.12(RE4) ; off-sheet RE4
RE5: D6.1(A) U1.17(RE5) ; off-sheet RE5
RE6: D7.1(A) U1.19(RE6) ; off-sheet RE6
RE7: D8.1(A) U1.21(RE7) ; off-sheet RE7
S1GPO0: U5.3(INA) ; off-sheet S1GPO0
S1GPO0_ISO: R18.2 TP6.1 U5.14(OUTA) ; off-sheet S1GPO0_ISO
SCLK: U5.4(INB) ; off-sheet SCLK
SCLK_ISO: R19.2 TP7.1 U5.13(OUTB) ; off-sheet SCLK_ISO
SOP: R16.1 U1.23(SOP) ; off-sheet SOP
NetC22_1: C22.1 C23.1 D11.2(A) R23.2
NetD9_1: D9.1(A) R22.1
NetR11_2: R11.2 U1.13(RLIM)
NetR12_2: R12.2 U1.27(SIP)

Not connected (* = marked no-connect by the designer): U1 14(NC)*; U6 6(NC)* 11(NC)*

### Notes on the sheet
- All ceramic capacitors are X7R, Safety Factor >= 3
- (near U5) Digital Isolators
- Control Line Filters
- Serializer
- (near R1) Field Input Filters
- (near J1) Field Input Connectors
- (near R18) Sets fc = 42MHz
  Place close to SN65HVS885
- Field Power Connectors
- (near R19) Sets fc = 42MHz
  Place close to SN65HVS885
- (near R20) Sets fc = 42MHz
  Place close to SN65HVS885
- (near C16) Sets fc = 42MHz
  Place close to ISO7141CC
- (near R11) Sets I_in = 2.04mA
- EMC Transient Protection for Field Power
- (near D1) Field Input Return LEDs

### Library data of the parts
C1-C8 = 202R18W102KV4E: CAP, CERM, 1000pF, 2KV 10% X7R 1206; Manufacturer: Johanson Dielectrics Inc; Polarized: N; CompType: Capacitor; Cap_F: 0.000000001; Tolerance_%: 0
C10 C19 C21 C25 C26 = GRM155R71C104KA88D: as C11 on sheet SAT0060 Sheet1
C12-C14 C16 = GRM1555C1H470JZ01: CAP, CERM, 47pF, 50V, +/-5%, C0G/NP0, 0402; Manufacturer: MuRata; Polarized: N; CompType: Capacitor; U/M: EA; Cap_F: 0.000000000047; Tolerance_%: 5; ESR_Ohm: 0.045; Value1: 0.045 ohm; VDC_V: 50; TaMin_C: -55; TaMax_C: 125
C20 C22-C24 = GRM21AR72A224KAC5L: CAP, CERM, 0.22uF, 100V, +/-10%, X7R, 0805; Manufacturer: MuRata; Polarized: N; CompType: Capacitor; U/M: EA; Cap_F: 0.00000022; Tolerance_%: 10; Value1: Unknown; VDC_V: 100; TaMin_C: -55; TaMax_C: 125; Cap_Case: 0805
C29 C31 = Capacitor: as C32 on sheet SAT0060 Sheet1
D1-D8 = SML-P12PTT86: LED GREEN 0.2MM 13MCD 0402 SMD; Manufacturer: Rohm Semiconductor; Voltage - Forward (Vf) Typ: 2.2V; Current - Test: 20mA; Wavelength - Dominant: 560nm; Lens Type: Clear; Lens Style/Size: Square with Flat Top, 0.6mm
D9 = SML-P12VTT86: LED RED 0.2MM 60MCD 0402 SMD; Manufacturer: Rohm Semiconductor; Voltage - Forward (Vf) Typ: 2V; Current - Test: 20mA; Wavelength - Dominant: 630nm; Lens Type: Clear; Lens Style/Size: Square with Flat Top, 0.6mm
D11 = BYM10-1000-E3/97: Diode, P-N, 1000V, 1A, 2.67x5.2mm; Manufacturer: Vishay-Semiconductor; U/M: EA; Vf_V: 1.2; Value2: 1.2V; Io_A: 1; Vr_V: 1000; TJmax_C: 175; RJC_CperW: 75
D12 = SMCJ33CA: Diode, TVS, Bi, 33V, 1500W, SMC; Manufacturer: Bourns; U/M: EA; Power_W: 1500; Vr_V: 33
J1 = 1725711: Terminal Block, 8x1, 2.54 mm, TH; Manufacturer: Phoenix Contact; U/M: EA
J2 J3 = 1725656: Header, 2 Pos, 6A, 63V, TH; Manufacturer: Phoenix Contact; SymbolCreator: a0412235; U/M: EA
R1-R8 = MMA02040C1201FB300: RES, 1.20k ohm, 1%, 0.25W, 1.4x3.6mm; Manufacturer: Vishay/Beyschlag; CompType: Resistor; Res_ohm: 1200; Value_Code: 1k20; Tolerance_%: 1; Power_W: 0.25; VDC_V: 200; TempCo: 50 ppm/C; U/M: EA
R9 R10 R12 = CRCW040210K0FKED: RES, 10.0k ohm, 1%, 0.063W, 0402; Manufacturer: Vishay-Dale; CompType: Resistor; Res_ohm: 10000; Value_Code: 10k0; Tolerance_%: 1; Power_W: 0.063; VDC_V: 50; TempCo: 100 ppm/C; EIA_Code: E96; U/M: EA
R11 = CRCW040244K2FKED: RES, 44.2k ohm, 1%, 0.063W, 0402; Manufacturer: Vishay-Dale; CompType: Resistor; Res_ohm: 44200; Value_Code: 44k2; Tolerance_%: 1; Power_W: 0.063; VDC_V: 50; TempCo: 100 ppm/C; EIA_Code: E96; U/M: EA
R16 R18-R20 = CRCW040280R6FKED: RES, 80.6 ohm, 1%, 0.063W, 0402; Manufacturer: Vishay-Dale; CompType: Resistor; Value_Code: 80R6; Tolerance_%: 1; Power_W: 0.063; VDC_V: 50; TempCo: 100 ppm/C; EIA_Code: E96; U/M: EA
R22 = CRCW04021K15FKED: RES, 1.15k ohm, 1%, 0.063W, 0402; Manufacturer: Vishay-Dale; CompType: Resistor; Res_ohm: 1150; Value_Code: 1k15; Tolerance_%: 1; Power_W: 0.063; VDC_V: 50; TempCo: 100 ppm/C; EIA_Code: E96; U/M: EA
R23 = MMB02070C5609FB200: RES, 56.0 ohm, 1%, 0.4W, 2.2x5.8mm; Manufacturer: Vishay/Beyschlag; CompType: Resistor; Res_ohm: 56; Value_Code: 56R0; Tolerance_%: 1; Power_W: 0.4; VDC_V: 300; TempCo: 50 ppm/C; U/M: EA
TP6-TP9 = 5003: as TP4 on sheet SAT0060 Sheet1
U1 = SN65HVS885PWP: 34 V, Digital-Input Serializer for 5V Systems, PWP0028E; Alternate Manufacturer: None; Manufacturer: Texas Instruments; SymbolCreator: a0411947; CompType: IC; U/M: EA
U5 = ISO7141CCDBQ: 4242-VPK Small-Footprint and Low-Power Quad Channels Digital Isolators, DBQ0016A; Alternate Manufacturer: None; Manufacturer: Texas Instruments; SymbolCreator: a0799628; CompType: IC; U/M: EA
U6 = ISO7131CCDBQ: 4242-VPK Small-Footprint and Low-Power Triple Channels Digital Isolators, DBQ0016A; Alternate Manufacturer: None; Manufacturer: Texas Instruments; SymbolCreator: a0799628; CompType: IC; U/M: EA

## Sheet Hardware_ANSI-B.SchDoc
size 431 x 279 mm; Date: Not shown in title block; ApprovedBy: Not shown in title block; CheckedBy: Not shown in title block; Author: Not shown in title block; CompanyName: Not shown in title block; Engineer: Not shown in title block; Organization: Not shown in title block; Address1: Not shown in title block; Address2: Not shown in title block; Address3: Not shown in title block; Address4: Not shown in title block; DocumentNumber: 1; Revision: Use project parameter SCH_Rev; SheetNumber: 1; SheetTotal: 1; PageSetup: Record=PageOptions|CenterHorizontal=True|CenterVertical=True|PrintScale=1.00|XCorrection=1.00|YCorrection=1.00|PrintKind=0|BorderSize=5000000|LeftOffset=0|BottomOffset=0|Orientation=2|PaperLength=1000|PaperWidth=1000|Scale=100|PaperSource=15|PrintQuality=600|MediaType=1|DitherType=10|PaperKind=Letter|PrintScaleMode=1
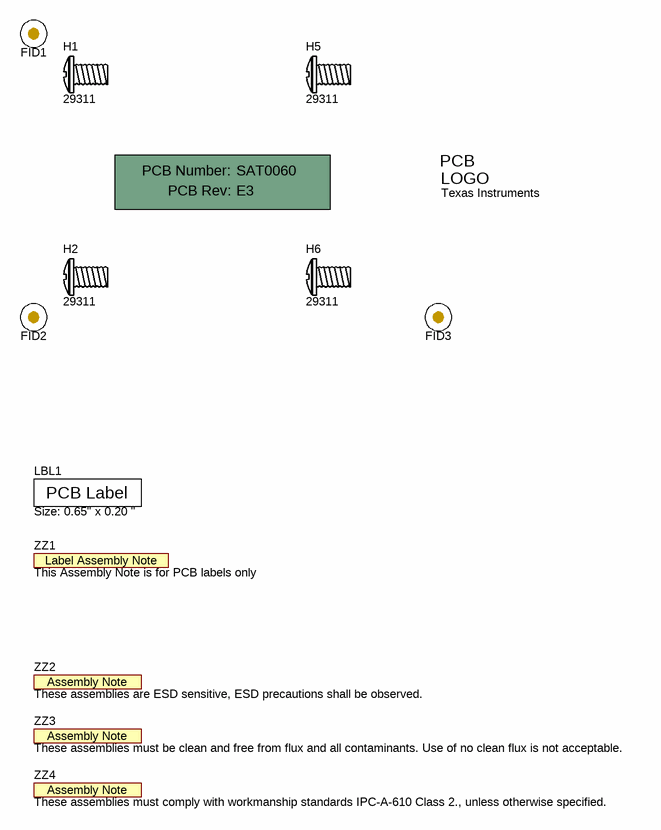
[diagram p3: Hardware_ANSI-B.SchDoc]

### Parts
!PCB1  Printed Circuit Board  (value not drawn)  (mechanical)
FID1  Fiducial  [Fiducial10-20]  (value not drawn)
FID2  Fiducial  [Fiducial10-20]  (value not drawn)
FID3  Fiducial  [Fiducial10-20]  (value not drawn)
H1  29311  [Keystone29311]
H2  29311  [Keystone29311]
H5  29311  [Keystone29311]
H6  29311  [Keystone29311]
LBL1  Size: 0.65" x 0.20 "  [Label_650x200]
Logo1  Texas Instruments  [TI_Stacked_Overlay_Small_Vertical]  (no BOM)
ZZ1  This Assembly Note is for PCB labels only  [AssemblyNoteLabel]  (no BOM)
ZZ2  These assemblies are ESD sensitive, ESD precautions shall be observed.  [AssemblyNote]  (no BOM)
ZZ3  These assemblies must be clean and free from flux and all contaminants. Use of no clean flux is not acceptable.  [AssemblyNote]  (no BOM)
ZZ4  These assemblies must comply with workmanship standards IPC-A-610 Class 2., unless otherwise specified.  [AssemblyNote]  (no BOM)

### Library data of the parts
!PCB1 = PCB: Manufacturer: Any; PartNumber: SAT0060; SymbolCreator: a0412235
FID1-FID3 = Fiducial: Fiducial mark.  There is nothing to buy or mount.; SymbolCreator: codlsc
H1 H2 H5 H6 = 29311: Screw Pan Head M3; Manufacturer: Keystone; CompType: Hardware; SymbolCreator: a0412235
LBL1 = THT-14-423-10: Thermal Transfer Printable Labels, 0.650" W x 0.200" H - 10,000 per roll; Manufacturer: Brady; SymbolCreator: a0412235; CompType: Label
Logo1 = TI_Logo: Texas Instrument Corporate Signature; SymbolCreator: codlsc
ZZ1 = AssemblyNoteLabel: SymbolCreator: a0412235
ZZ2-ZZ4 = AssemblyNote: SymbolCreator: codlsc

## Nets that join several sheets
3V3: SAT0060 Sheet1 (7 pins), SAT0060 Sheet2 (6 pins)
5V_ISO: SAT0060 Sheet1 (C38.1 D14.1 D15.1 TP2.1), SAT0060 Sheet2 (12 pins)
25V_ISO: SAT0060 Sheet1 (C37.1 D13.1 D16.1 TP11.1), SAT0060 Sheet2 (C24.1 R23.1)
ISO_GND: SAT0060 Sheet1 (9 pins), SAT0060 Sheet2 (35 pins)
PLC_GND: SAT0060 Sheet1 (37 pins), SAT0060 Sheet2 (6 pins)
DB0_PLC: SAT0060 Sheet1 (J4.27), SAT0060 Sheet2 (U6.3)
DB1_PLC: SAT0060 Sheet1 (J4.29), SAT0060 Sheet2 (U6.4)
MISO: SAT0060 Sheet1 (J4.5), SAT0060 Sheet2 (U5.6)
nCS0: SAT0060 Sheet1 (J4.1), SAT0060 Sheet2 (U5.5)
nSDRDY: SAT0060 Sheet1 (J4.6), SAT0060 Sheet2 (U6.5)
S1GPO0: SAT0060 Sheet1 (J4.28), SAT0060 Sheet2 (U5.3)
SCLK: SAT0060 Sheet1 (J4.3), SAT0060 Sheet2 (U5.4)

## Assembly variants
001: all parts fitted
DNP: not fitted D15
